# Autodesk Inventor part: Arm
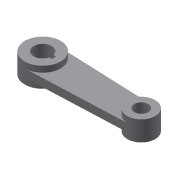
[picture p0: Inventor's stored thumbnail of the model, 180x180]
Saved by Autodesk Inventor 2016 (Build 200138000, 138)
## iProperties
Created: 2009-04
Part Number: Arm
Material: Generic
Document SubType Name: Modeling
Designer: Sham
Density: 1 g/cm^3
Sheet Metal Width: 0.000 mm
Sheet Metal Length: 0.000 mm
Sheet Metal Area: 0.000 mm^2
Sheet Metal Rule: Default_mm
Appearance: Default
Author: Sham
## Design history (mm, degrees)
sketch "Sketch1"
  geometry: L1 (27.436, 6.3)-(35.136, 6.3); L2 (35.136, 6.3)-(35.136, -6.3); L3 (35.136, -6.3)-(27.436, -6.3); C1 r 56.25 at (0, 0); C2 r 43.75 at (309, 0); C3 r 21.9 at (309, 0); A1 r 28.15 centre (0, 0) between (27.436, 6.3) and (27.436, -6.3); 1 further point
  constraints: 6 end point, 4 centre point, 3 coincident, 2 point on circle, 1 horizontal, 1 parallel, 1 perpendicular, 1 other
  dimensions: "d0" = 112.5 diameter of C1; "d2" = 87.5 diameter of C2; "d3" = 56.3 diameter of A1; "d4" = 43.8 diameter of C3; "d7" = 12.6 distance of L1.end L2.end; "d8" = 7.7 distance of L1.start L1.end; "d9" = 7.7 distance of L2.end L3.end
extrude "Extrusion1" join sketch "Sketch1" stored distance "d5" = 62.5; taper "d6" = 0 deg
sketch "Sketch2"
  geometry: L1 (2.275, 56.204)-(310.77, 43.714); L2 (2.275, -56.204)-(310.77, -43.714); A1 r 56.25 centre (0, 0) between (2.275, 56.204) and (2.275, -56.204) reference; A2 r 43.75 centre (309, 0) between (310.77, 43.714) and (310.77, -43.714) reference
  constraints: 4 end point, 4 point on circle, 4 tangent
extrude "Extrusion2" join sketch "Sketch2" stored distance "d10" = 25; taper "d11" = 0 deg
body "Solid1"
other parameters: "Thickness" = 0.5, "BendRadius" = 0.5 (= Thickness), "BendReliefWidth" = 0.5 (= Thickness), "BendReliefDepth" = 0.25 (= 0.5 x Thickness), "CornerReliefSize" = 2 (= 4 x Thickness), "SeamGap" = 0.01, "MinimumRemnant" = 1 (= 2 x Thickness), "TransitionRadius" = 0.5 (= BendRadius), "JacobiRadiusSize" = 0.5 (= BendRadius), "GapSize" = 0.5 (= Thickness)
